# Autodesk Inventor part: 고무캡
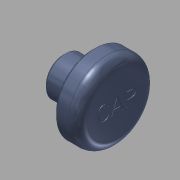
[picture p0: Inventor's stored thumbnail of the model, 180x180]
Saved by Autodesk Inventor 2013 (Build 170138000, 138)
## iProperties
Created: 2017-06
Part Number: 고무캡
Material: 고무
Document SubType Name: Modeling
Designer: mduedu
Density: 0.93 g/cm^3
Mass: 1.05558 g
Surface Area: 8.38717 cm^2
Volume: 1.13504 cm^3
Author: mduedu
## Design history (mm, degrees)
sketch "스케치1"
  geometry: L1 (0, 0)-(11, 0); L2 (11, 0)-(11, 8); L3 (11, 8)-(6.5, 8); L4 (0, 4)-(0, 0); L5 (0, 4)-(6, 4); L6 (6, 4)-(6, 7.5); L7 (6, 7.5)-(6.5, 7.5); L8 (6.5, 7.5)-(6.5, 8)
  constraints: 16 end point, 2 horizontal, 2 parallel, 2 perpendicular, 2 point on line, 1 vertical
  dimensions: "d0" = 16 diameter of L3 L1; "d2" = 8 diameter of L5 L1; "d6" = 5 distance between parallel lines of L2 L6; "d7" = 0.5 distance between parallel lines of L8 L6; "d8" = 15 diameter of L7 L1; "d9" = 6 distance between parallel lines of L6 L4
revolve "회전1" sketch "스케치1" stored, may be unused: angle "d10" = 90 deg
hole "구멍1" diameter "d22" = 5; stored, may be unused: countersink angle "d26" = 90 deg, drill point angle "d28" = 0 deg; dims "d23" = 6, "d24" = 4, "d25" = 2, "d27" = 6, "d30" = 10, "d31" = 10
chamfer "모따기1" distance "d13" = 0.5; stored, may be unused: second distance "d14" = 2, angle "d15" = 45 deg
fillet "모깎기3" dims "d29" = 1
fillet "모깎기1" dims "d16" = 0.1
fillet "모깎기2" dims "d17" = 2
sketch "스케치3"
  geometry: 2 further points
  constraints: 1 coincident, 1 other
feature "엠보싱1" sketch "스케치3" dims "d18" = 0.2, "d19" = 0
node "솔리드1"
